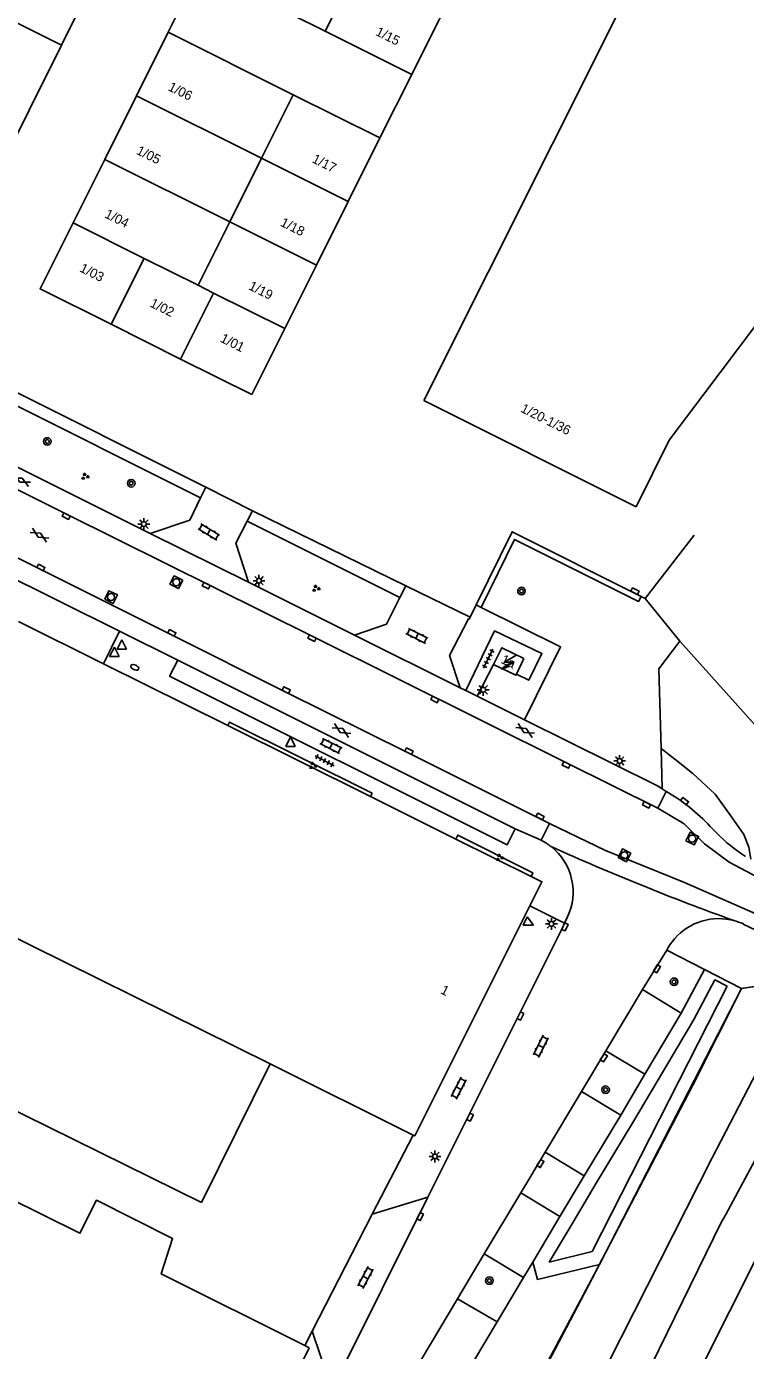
# Model space of a CAD drawing. Extents: x 135999 to 138000, y 396000 to 398501.
# Drawn here: x 136118.4 to 136194.3, y 397671.5 to 397811.3 of the extents above; entities that cross this region are included whole.
import ezdxf

# ---------------------------------------------------------------- set-up
doc = ezdxf.new("R2010")
doc.units = 0
for name, color, linetype in [('gg-afsc-hekwerk', 7, 'Continuous'), ('gg-anno-huisnummerreeks BGT', 7, 'Continuous'), ('gg-aspt-spoorlijn', 7, 'Continuous'), ('gg-bbg-gedigitaliseerde bebouwing', 7, 'Continuous'), ('gg-bbg-hoofdgebouw', 7, 'Continuous'), ('gg-bbg-tussenscheiding', 7, 'Continuous'), ('gg-knt-bronhoudergrens', 7, 'Continuous'), ('gg-knt-verharding', 7, 'Continuous'), ('gg-knt-verharding nz', 7, 'Continuous'), ('gt-grn-bladgrens', 7, 'Continuous'), ('gt-grn-groengrens', 7, 'Continuous'), ('gt-grn-vlakafsluiter', 7, 'Continuous'), ('gt-symb-boom', 7, 'Continuous'), ('gt-symb-brandkraan', 7, 'Continuous'), ('gt-symb-gesloten verharding', 7, 'Continuous'), ('gt-symb-groenvak', 7, 'Continuous'), ('gt-symb-klinker verharding', 7, 'Continuous'), ('gt-symb-kolk', 7, 'Continuous'), ('gt-symb-kolk center center', 7, 'Continuous'), ('gt-symb-lichtmast', 7, 'Continuous'), ('gt-symb-rioolschacht', 7, 'Continuous'), ('gt-symb-tegel verharding', 7, 'Continuous'), ('gt-symb-trafo symbool', 7, 'Continuous'), ('gt-symb-waterafsluiter', 7, 'Continuous'), ('gx-grn-maaiveld', 7, 'Continuous')]:
    doc.layers.add(name, color=color, linetype=linetype)

# ---------------------------------------------------------------- blocks, each defined once
blk = doc.blocks.new('gt0-BOOM')
at = {"layer": 'gt-symb-boom'}
for radius in [0.4, 0.2]:
    blk.add_circle((0, 0), radius, dxfattribs=at)
blk = doc.blocks.new('gt0-KOLK')
at = {"layer": 'gt-symb-kolk'}
blk.add_lwpolyline([(0, 0), (0.38, 0), (0.38, 0.4), (-0.38, 0.4), (-0.38, 0), (0, 0)], dxfattribs=at)
blk = doc.blocks.new('gt0-GRVAK')
at = {"layer": 'gt-symb-groenvak'}
for p, q in [((-0.11, 0.19), (-0.23, 0.24)), ((-0.18, 0.15), (0.09, 0.15)), ((-0.09, 0.21), (-0.16, 0.32)), ((-0.05, 0.21), (-0.05, 0.39)), ((0, 0.21), (0.06, 0.32)), ((0.02, 0.19), (0.13, 0.24)), ((0.26, -0.05), (0.2, 0.06)), ((0.3, -0.05), (0.3, 0.13)), ((0.35, -0.05), (0.41, 0.06)), ((-0.24, -0.23), (-0.36, -0.18)), ((-0.32, -0.26), (-0.05, -0.26)), ((-0.23, -0.21), (-0.29, -0.1)), ((-0.18, -0.2), (-0.18, -0.02)), ((-0.14, -0.21), (-0.07, -0.1)), ((-0.12, -0.23), (0, -0.18)), ((0.24, -0.07), (0.12, -0.02)), ((0.17, -0.11), (0.44, -0.11)), ((0.37, -0.07), (0.49, -0.02))]:
    blk.add_line(p, q, dxfattribs=at)
blk = doc.blocks.new('gt0-LMAST')
at = {"layer": 'gt-symb-lichtmast'}
for p, q in [((-0.18, 0.17), (-0.45, 0.44)), ((-0.01, 0.25), (-0.01, 0.62)), ((0.17, 0.17), (0.44, 0.44)), ((-0.26, 0), (-0.63, 0)), ((-0.18, -0.18), (-0.45, -0.45)), ((-0.01, -0.25), (-0.01, -0.63)), ((0.44, -0.45), (0.17, -0.18)), ((0.24, 0), (0.62, 0))]:
    blk.add_line(p, q, dxfattribs=at)
blk.add_circle((-0.01, 0), 0.25, dxfattribs=at)
blk = doc.blocks.new('gt0-RS')
at = {"layer": 'gt-symb-rioolschacht'}
blk.add_lwpolyline([(-0.5, -0.5), (0.5, -0.5), (0.5, 0.5), (-0.5, 0.5)], close=True, dxfattribs=at)
blk.add_circle((0, 0), 0.375, dxfattribs=at)
blk = doc.blocks.new('gt0-GESVH1')
at = {"layer": 'gt-symb-gesloten verharding'}
for p, q in [((-0.99, -0.26), (0.01, 0.24)), ((0.01, -0.26), (-0.99, 0.24)), ((0.01, 0.24), (1.01, -0.26)), ((1.01, 0.24), (0.01, -0.26))]:
    blk.add_line(p, q, dxfattribs=at)
blk = doc.blocks.new('gt0-KL1')
at = {"layer": 'gt-symb-klinker verharding'}
for p, q in [((-1.15, 0.3), (1.15, 0.3)), ((-1, -0.3), (-1, 0.3)), ((-0.5, 0.3), (-0.5, 0.45)), ((0, -0.3), (0, 0.3)), ((0.5, 0.3), (0.5, 0.45)), ((1, -0.3), (1, 0.3)), ((-1.15, -0.3), (1.15, -0.3)), ((-0.5, -0.45), (-0.5, -0.3)), ((0.5, -0.45), (0.5, -0.3))]:
    blk.add_line(p, q, dxfattribs=at)
blk = doc.blocks.new('gt0-TEG1')
at = {"layer": 'gt-symb-tegel verharding'}
for p, q in [((-1.12, 0), (1.13, 0)), ((-0.9, -0.25), (-0.9, 0.25)), ((-0.45, -0.25), (-0.45, 0.25)), ((0, -0.25), (0, 0.25)), ((0.45, -0.25), (0.45, 0.25)), ((0.9, -0.25), (0.9, 0.25))]:
    blk.add_line(p, q, dxfattribs=at)
blk = doc.blocks.new('gt0-HSP')
at = {"layer": 'gt-symb-trafo symbool'}
for points in [[(0.77, 0.75), (-0.53, 0), (0.47, 0), (-0.83, -0.75)], [(-0.22, -0.24), (-0.83, -0.75), (-0.08, -0.48)]]:
    blk.add_lwpolyline(points, dxfattribs=at)
blk = doc.blocks.new('gt0-WAFSL')
at = {"layer": 'gt-symb-waterafsluiter'}
for p, q in [((-0.5, -0.33), (0, 0.67)), ((0, 0.67), (0.5, -0.33)), ((0.5, -0.33), (-0.5, -0.33))]:
    blk.add_line(p, q, dxfattribs=at)
blk = doc.blocks.new('gt0-BR')
at = {"layer": 'gt-symb-brandkraan'}
for centre, radius, start, end in [((-0.24, 0), 0.206, 107.5669, 252.4331), ((0.6, -2.66), 3, 106.892, 107.5669), ((0, -0.69), 0.938, 73.108, 106.892), ((-0.6, -2.66), 3, 72.4331, 73.108), ((0.24, 0), 0.206, 287.567, 72.4331), ((0.6, 2.66), 3, 252.4331, 253.108), ((0, 0.69), 0.938, 253.108, 286.8921), ((-0.6, 2.66), 3, 286.8921, 287.567)]:
    blk.add_arc(centre, radius, start, end, dxfattribs=at)
blk = doc.blocks.new('gt0-KOLKCC')
at = {"layer": 'gt-symb-kolk center center'}
blk.add_lwpolyline([(-0.38, 0.2), (0.38, 0.2), (0.38, -0.2), (-0.38, -0.2)], close=True, dxfattribs=at)

msp = doc.modelspace()

# ---------------------------------------------------------------- linework, layer by layer
at = {"layer": 'gg-afsc-hekwerk'}
for p, q in [((136159.21, 397694.26), (136154.9, 397685.9)), ((136154.9, 397685.9), (136148.56, 397673.57)), ((136148.56, 397673.57), (136147.77, 397672.04))]:
    msp.add_line(p, q, dxfattribs=at)
msp.add_lwpolyline([(136206.22, 397710.07), (136203.26, 397711.27), (136196.98, 397710.23), (136193.86, 397709.75), (136188.71, 397699.53), (136178.32, 397679.53), (136172.59, 397668.77), (136160.48, 397645.24), (136132.77, 397588.81), (136102.14, 397526.87), (136090.23, 397502.97), (136088.59, 397499.81), (136086.91, 397496.59), (136075.23, 397472.87), (136076.15, 397472.41)], dxfattribs=at)
at = {"layer": 'gg-aspt-spoorlijn'}
msp.add_lwpolyline([(136075.9, 397441.46), (136078.9, 397447.5), (136110.62, 397511), (136126.65, 397543.4), (136168.42, 397626.98), (136182.98, 397656.49), (136206.97, 397704.32), (136208.88, 397708.17)], dxfattribs=at)
at = {"layer": 'gg-bbg-gedigitaliseerde bebouwing'}
msp.add_lwpolyline([(136103.07, 397699.88), (136104.63, 397703.04), (136136.86, 397687.15)], dxfattribs=at)
at = {"layer": 'gg-bbg-hoofdgebouw'}
for p, q in [((136122.09, 397809.32), (136126.17, 397817.51)), ((136133.36, 397810.68), (136136.71, 397817.39)), ((136162.41, 397812.93), (136159.06, 397806.23)), ((136130.02, 397803.98), (136133.36, 397810.68)), ((136113.97, 397793.01), (136122.09, 397809.32)), ((136159.06, 397806.23), (136155.71, 397799.52)), ((136126.66, 397797.26), (136130.02, 397803.98)), ((136155.71, 397799.52), (136152.36, 397792.81)), ((136123.32, 397790.57), (136126.66, 397797.26)), ((136152.36, 397792.81), (136149.01, 397786.09)), ((136149.01, 397786.09), (136145.66, 397779.39)), ((136134.67, 397776.18), (136127.34, 397779.85)), ((136145.66, 397779.39), (136142.18, 397772.43)), ((136142.18, 397772.43), (136134.67, 397776.18)), ((136160.35, 397771.8), (136182.75, 397760.59)), ((136117.58, 397748.46), (136126.54, 397744)), ((136126.54, 397744), (136139.64, 397737.49)), ((136170.9, 397744.56), (136170.1, 397742.9)), ((136139.64, 397737.49), (136154.71, 397729.99)), ((136154.71, 397729.99), (136163.73, 397725.51)), ((136163.73, 397725.51), (136171.68, 397721.55)), ((136144.13, 397701.77), (136136.86, 397687.15)), ((136159.21, 397694.26), (136144.13, 397701.77)), ((136148.25, 397671.8), (136138.89, 397653.04)), ((136147.77, 397672.04), (136148.25, 397671.8))]:
    msp.add_line(p, q, dxfattribs=at)
for points in [[(136182.75, 397760.59), (136186.24, 397767.61), (136204.5, 397791.9), (136214.73, 397812.29), (136187.44, 397825.96), (136160.35, 397771.8)], [(136127.34, 397779.85), (136119.84, 397783.6), (136123.32, 397790.57)], [(136167.69, 397743.95), (136168.55, 397745.7), (136170.9, 397744.56)], [(136170.1, 397742.9), (136170.05, 397742.8), (136167.69, 397743.95)], [(136171.68, 397721.55), (136172.79, 397721), (136171.52, 397718.47)], [(136171.52, 397718.47), (136159.38, 397694.17), (136159.21, 397694.26)], [(136100.84, 397695.39), (136124.04, 397683.89), (136125.78, 397687.38), (136133.83, 397683.35), (136132.62, 397679.61), (136147.77, 397672.04)]]:
    msp.add_lwpolyline(points, dxfattribs=at)
at = {"layer": 'gg-bbg-tussenscheiding'}
for p, q in [((136136.71, 397817.39), (136149.92, 397810.79)), ((136149.92, 397810.79), (136153.27, 397817.49)), ((136122.09, 397809.32), (136109.54, 397815.57)), ((136133.36, 397810.68), (136146.56, 397804.09)), ((136149.92, 397810.79), (136159.06, 397806.23)), ((136130.02, 397803.98), (136143.21, 397797.38)), ((136143.21, 397797.38), (136146.56, 397804.09)), ((136146.56, 397804.09), (136155.71, 397799.52)), ((136126.66, 397797.26), (136139.86, 397790.67)), ((136139.86, 397790.67), (136143.21, 397797.38)), ((136143.21, 397797.38), (136152.36, 397792.81)), ((136123.32, 397790.57), (136130.82, 397786.81)), ((136136.51, 397783.97), (136139.86, 397790.67)), ((136139.86, 397790.67), (136149.01, 397786.09)), ((136127.34, 397779.85), (136130.82, 397786.81)), ((136130.82, 397786.81), (136136.51, 397783.97)), ((136134.67, 397776.18), (136138.15, 397783.15)), ((136136.51, 397783.97), (136138.15, 397783.15)), ((136138.15, 397783.15), (136145.66, 397779.39)), ((136097.81, 397724.7), (136144.13, 397701.77))]:
    msp.add_line(p, q, dxfattribs=at)
at = {"layer": 'gg-knt-bronhoudergrens'}
msp.add_line((136193.86, 397709.75), (136198.36, 397710.41), dxfattribs=at)
msp.add_lwpolyline([(136193.86, 397709.75), (136186.37, 397695.18), (136178.88, 397680.61)], dxfattribs=at)
at = {"layer": 'gg-knt-verharding'}
for p, q in [((136137.34, 397762.67), (136114.96, 397773.86)), ((136114.47, 397766.24), (136131.46, 397757.78)), ((136136.78, 397761.53), (136137.34, 397762.67)), ((136137.34, 397762.67), (136142.24, 397760.17)), ((136142.24, 397760.17), (136141.69, 397759.08)), ((136158.45, 397752.25), (136142.24, 397760.17)), ((136141.82, 397752.62), (136131.46, 397757.78)), ((136183.69, 397750.91), (136188.86, 397757.6)), ((136128.22, 397747.46), (136108.75, 397757.15)), ((136141.82, 397752.62), (136153.01, 397747.05)), ((136157.82, 397751), (136158.45, 397752.25)), ((136183.69, 397750.91), (136183.26, 397751.13)), ((136165.23, 397748.93), (136165.87, 397750.23)), ((136128.22, 397747.46), (136126.54, 397744)), ((136128.22, 397747.46), (136134.36, 397744.39)), ((136164.18, 397741.48), (136153.01, 397747.05)), ((136169.99, 397726.59), (136134.36, 397744.39)), ((136163.04, 397744.87), (136164.18, 397741.48)), ((136165.96, 397740.6), (136167.69, 397743.95)), ((136164.18, 397741.48), (136164.76, 397741.19)), ((136164.76, 397741.19), (136165.96, 397740.6)), ((136165.96, 397740.6), (136170.95, 397738.11)), ((136185.02, 397728.76), (136185.91, 397730.54)), ((136185.5, 397730.8), (136185.91, 397730.54)), ((136172.71, 397725.38), (136173.61, 397727.16)), ((136191.24, 397726.14), (136190.56, 397726.85)), ((136169.99, 397726.59), (136172.71, 397725.38)), ((136172.71, 397725.38), (136172.76, 397725.36)), ((136175.19, 397716.62), (136171.52, 397718.47)), ((136175.47, 397717.22), (136175.19, 397716.62)), ((136193.04, 397716.91), (136192.69, 397716.99)), ((136194.05, 397716.54), (136200.08, 397713.62)), ((136185.97, 397713.78), (136183.4, 397709.62)), ((136183.4, 397709.62), (136187.5, 397707.13)), ((136187.5, 397707.13), (136183.67, 397700.68)), ((136179.55, 397703.16), (136176.97, 397698.87)), ((136183.67, 397700.68), (136179.55, 397703.16)), ((136176.97, 397698.87), (136181.11, 397696.35)), ((136181.11, 397696.35), (136177.24, 397689.97)), ((136173.14, 397692.46), (136170.57, 397688.16)), ((136177.24, 397689.97), (136173.14, 397692.46)), ((136170.57, 397688.16), (136174.69, 397685.66)), ((136174.69, 397685.66), (136171.83, 397680.86)), ((136166.7, 397681.71), (136163.89, 397676.99)), ((136170.84, 397679.21), (136166.7, 397681.71)), ((136171.83, 397680.86), (136170.84, 397679.21)), ((136163.89, 397676.99), (136168.07, 397674.54)), ((136168.07, 397674.54), (136164.19, 397668.06))]:
    msp.add_line(p, q, dxfattribs=at)
for points in [[(136047.26, 397797.39), (136054.37, 397793.87), (136082.97, 397779.59), (136092.95, 397774.6), (136109.76, 397766.26), (136122.69, 397759.78), (136148.62, 397746.9), (136175.45, 397733.51), (136185.02, 397728.76)], [(136173.61, 397727.16), (136158.68, 397734.61), (136145.72, 397741.06), (136133.65, 397747.1), (136119.84, 397753.99), (136106.87, 397760.47), (136093.91, 397766.92), (136089.99, 397768.89), (136080.05, 397773.76), (136065.32, 397781.11), (136054.8, 397786.33)], [(136131.46, 397757.78), (136135.63, 397759.17), (136136.78, 397761.53)], [(136141.69, 397759.08), (136140.51, 397756.74), (136141.82, 397752.62)], [(136183.26, 397751.13), (136169.64, 397757.95), (136165.87, 397750.23)], [(136153.01, 397747.05), (136156.4, 397748.19), (136157.82, 397751)], [(136163.04, 397744.87), (136165.04, 397748.76), (136165.13, 397748.72), (136165.23, 397748.93)], [(136164.76, 397741.19), (136167.81, 397747.49), (136172.79, 397745.1), (136171.41, 397742.27), (136170.1, 397742.9)], [(136134.36, 397744.39), (136133.51, 397742.71), (136169.14, 397724.9), (136169.99, 397726.59)], [(136170.95, 397738.11), (136185.01, 397731.12), (136185.5, 397730.8)], [(136154.71, 397729.99), (136154.87, 397730.35), (136139.83, 397737.86), (136139.64, 397737.49)], [(136171.68, 397721.55), (136171.83, 397721.96), (136163.93, 397725.92), (136163.73, 397725.51)]]:
    msp.add_lwpolyline(points, dxfattribs=at)
for centre, radius, start, end in [((136175.75, 397712.95), 20.31, 43.1848, 59.99), ((136201.85, 397736.1), 14.54, 223.1998, 238.6522), ((136170.01, 397719.98), 6.04, 51.6768, 62.9052), ((136285.79, 397973.51), 272.85, 245.7582, 250.1275), ((136169.96, 397719.91), 6.13, 334.0081, 51.7298), ((136191.46, 397710.92), 6.19, 78.5243, 142.8464), ((136191.47, 397710.94), 6.17, 65.231, 75.283), ((136191.46, 397710.92), 6.19, 142.8656, 152.48)]:
    msp.add_arc(centre, radius, start, end, dxfattribs=at)
at = {"layer": 'gg-knt-verharding nz'}
for p, q in [((136183.4, 397709.62), (136179.55, 397703.16)), ((136176.97, 397698.87), (136173.14, 397692.46)), ((136160.76, 397687.7), (136150.62, 397667.4)), ((136154.9, 397685.9), (136160.76, 397687.7)), ((136170.57, 397688.16), (136166.7, 397681.71)), ((136163.89, 397676.99), (136160.04, 397670.53)), ((136150.62, 397667.4), (136148.56, 397673.57))]:
    msp.add_line(p, q, dxfattribs=at)
for points in [[(136185.02, 397728.76), (136187.82, 397727.13), (136189.95, 397725), (136192.56, 397723.07), (136196.21, 397721.12), (136204.45, 397717.04), (136209.71, 397714.25)], [(136173.61, 397727.16), (136179.49, 397724.29), (136187.85, 397720.92), (136196.82, 397716.99), (136203.48, 397713.62), (136208.21, 397711.23)], [(136175.19, 397716.62), (136174.95, 397716.08), (136160.76, 397687.7)]]:
    msp.add_lwpolyline(points, dxfattribs=at)
at = {"layer": 'gt-grn-bladgrens'}
msp.add_line((136191.71, 397685.03), (136192.19, 397685.88), dxfattribs=at)
at = {"layer": 'gt-grn-groengrens'}
for p, q in [((136136.78, 397761.53), (136114.39, 397772.74)), ((136157.82, 397751), (136141.69, 397759.08)), ((136183.69, 397750.91), (136187.36, 397746.41)), ((136165.87, 397750.23), (136166.4, 397749.96)), ((136187.36, 397746.41), (136206.95, 397724.49)), ((136185.5, 397730.8), (136185.38, 397735.08)), ((136185.97, 397713.78), (136189.94, 397711.75)), ((136189.94, 397711.75), (136187.5, 397707.13)), ((136189.94, 397711.75), (136193.86, 397709.75)), ((136178.1, 397681.97), (136192.35, 397709.97)), ((136183.67, 397700.68), (136181.11, 397696.35)), ((136177.24, 397689.97), (136174.69, 397685.66)), ((136171.83, 397680.86), (136172.33, 397679)), ((136172.33, 397679), (136178.88, 397680.61)), ((136170.84, 397679.21), (136168.07, 397674.54))]:
    msp.add_line(p, q, dxfattribs=at)
for points in [[(136183.26, 397751.13), (136182.99, 397750.59), (136169.92, 397757.14), (136166.4, 397749.96)], [(136170.95, 397738.11), (136174.77, 397745.8), (136166.4, 397749.96)], [(136187.36, 397746.41), (136185.14, 397743.48), (136185.38, 397735.08)], [(136185.38, 397735.08), (136186.84, 397733.95), (136188.71, 397732.44), (136191.09, 397730.24), (136192.8, 397727.86), (136194.09, 397725.99), (136194.63, 397724.65), (136194.83, 397723.4)], [(136178.1, 397681.97), (136173.57, 397680.85), (136175.98, 397684.89), (136178.52, 397689.2), (136182.4, 397695.58), (136184.96, 397699.92), (136188.81, 397706.4), (136191.05, 397710.64), (136192.35, 397709.97)]]:
    msp.add_lwpolyline(points, dxfattribs=at)
at = {"layer": 'gt-grn-vlakafsluiter'}
msp.add_line((136158.45, 397752.25), (136165.23, 397748.93), dxfattribs=at)
msp.add_lwpolyline([(136178.88, 397680.61), (136166.53, 397657.01), (136160.48, 397645.24), (136147.38, 397618.57), (136132.77, 397588.81), (136103.22, 397529.06), (136086.99, 397496.75)], dxfattribs=at)
at = {"layer": 'gx-grn-maaiveld'}
msp.add_line((136191.71, 397685.03), (136168.74, 397638.06), dxfattribs=at)
for points in [[(136079.12, 397470.95), (136089.3, 397490.11), (136093.09, 397497.58), (136116.32, 397543.68), (136148.79, 397608.63), (136171.6, 397654), (136190.78, 397691.87), (136195.5, 397701), (136198.41, 397705.89), (136200.96, 397709.86), (136201.44, 397710.49), (136201.81, 397710.81)], [(136204.48, 397706.86), (136204.15, 397706.41), (136203.28, 397706.22), (136202.24, 397704.56), (136192.19, 397685.88)]]:
    msp.add_lwpolyline(points, dxfattribs=at)

# ---------------------------------------------------------------- block references
at = {"layer": 'gt-symb-boom'}
for p in [(136120.6, 397767.48), (136129.46, 397763.07), (136170.64, 397751.69), (136186.74, 397710.44), (136179.52, 397699.05), (136167.25, 397678.89)]:
    msp.add_blockref('gt0-BOOM', p, dxfattribs=at)
at = {"layer": 'gt-symb-brandkraan', "rotation": -24.77113890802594}
msp.add_blockref('gt0-BR', (136129.83, 397743.63), dxfattribs=at)
at = {"layer": 'gt-symb-gesloten verharding'}
for p, rotation in [((136117.82, 397763.41), -26.02719868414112), ((136119.77, 397757.6), -31.003067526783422), ((136151.64, 397736.98), -31.003067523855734), ((136171.02, 397736.99), -31.003067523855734)]:
    msp.add_blockref('gt0-GESVH1', p, dxfattribs=dict(at, rotation=rotation))
at = {"layer": 'gt-symb-groenvak'}
for p in [(136124.57, 397763.78), (136148.95, 397751.96), (136148.62, 397733.26), (136168.32, 397723.55)]:
    msp.add_blockref('gt0-GRVAK', p, dxfattribs=at)
at = {"layer": 'gt-symb-klinker verharding'}
for p, rotation in [((136137.65, 397757.92), -31.003067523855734), ((136159.61, 397746.95), -26.565051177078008), ((136150.54, 397735.34), 153.46056160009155), ((136172.68, 397703.63), -116.41137489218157), ((136164.01, 397699.21), -117.46222718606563), ((136154.17, 397679.22), -118.153346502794)]:
    msp.add_blockref('gt0-KL1', p, dxfattribs=dict(at, rotation=rotation))
at = {"layer": 'gt-symb-kolk'}
for p, rotation in [((136122.69, 397759.78), 153.38370037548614), ((136119.84, 397753.99), -26.565051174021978), ((136137.46, 397752.44), 153.58862510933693), ((136182.53, 397751.5), -26.60114300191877), ((136133.65, 397747.1), -26.488178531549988), ((136148.62, 397746.9), 153.58862511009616), ((136145.72, 397741.06), -26.565051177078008), ((136161.59, 397740.43), 153.51182146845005), ((136158.68, 397734.61), -26.488178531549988), ((136175.45, 397733.51), 153.46056159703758), ((136187.73, 397729.36), -37.23665897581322), ((136172.51, 397727.71), -26.539438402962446), ((136183.93, 397729.3), 153.63994178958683), ((136175.04, 397716.32), -115.33527699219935), ((136184.78, 397711.92), -120.79671391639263), ((136179.16, 397702.53), -121.79891282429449), ((136172.47, 397691.36), -121.13079914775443)]:
    msp.add_blockref('gt0-KOLK', p, dxfattribs=dict(at, rotation=rotation))
at = {"layer": 'gt-symb-kolk center center'}
for p, rotation in [((136170.54, 397706.83), 64.02428534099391), ((136165.21, 397696.15), -116.82140642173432), ((136159.95, 397685.66), 63.306770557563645)]:
    msp.add_blockref('gt0-KOLKCC', p, dxfattribs=dict(at, rotation=rotation))
at = {"layer": 'gt-symb-lichtmast'}
for p in [(136130.8, 397758.76), (136142.95, 397752.78), (136166.61, 397741.27), (136181.01, 397733.76), (136173.81, 397716.55), (136161.52, 397692.01)]:
    msp.add_blockref('gt0-LMAST', p, dxfattribs=at)
at = {"layer": 'gt-symb-rioolschacht'}
for p, rotation in [((136134.22, 397752.62), 152.53777281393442), ((136127.33, 397751.06), -25.71951295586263), ((136188.65, 397725.56), -26.488178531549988), ((136181.5, 397723.79), -27.179734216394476)]:
    msp.add_blockref('gt0-RS', p, dxfattribs=dict(at, rotation=rotation))
at = {"layer": 'gt-symb-tegel verharding'}
for p, rotation in [((136167.14, 397744.55), -116.15525375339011), ((136149.86, 397733.78), -27.769212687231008)]:
    msp.add_blockref('gt0-TEG1', p, dxfattribs=dict(at, rotation=rotation))
at = {"layer": 'gt-symb-trafo symbool'}
msp.add_blockref('gt0-HSP', (136169.37, 397744.2), dxfattribs=at)
at = {"layer": 'gt-symb-waterafsluiter'}
for p in [(136128.46, 397745.88), (136127.68, 397745.1), (136146.26, 397735.62)]:
    msp.add_blockref('gt0-WAFSL', p, dxfattribs=at)
at = {"layer": 'gt-symb-waterafsluiter', "rotation": -116.56505117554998}
msp.add_blockref('gt0-WAFSL', (136171.32, 397716.71), dxfattribs=at)

# ---------------------------------------------------------------- texts
at = {"layer": 'gg-anno-huisnummerreeks BGT'}
for s, rotation, p in [('1/15', 333.5, (136155.16, 397810.41)), ('1/06', 333.5, (136133.27, 397804.59)), ('1/05', 333.5, (136129.92, 397797.87)), ('1/17', 333.5, (136148.46, 397796.99)), ('1/04', 333.5, (136126.57, 397791.17)), ('1/18', 333.5, (136145.11, 397790.28)), ('1/03', 333.4, (136123.94, 397785.46)), ('1/19', 333.5, (136141.76, 397783.57)), ('1/02', 333.4, (136131.35, 397781.76)), ('1/01', 333.4, (136138.77, 397778.05)), ('1/20-1/36', 333.4, (136170.47, 397770.65)), ('1a', 334, (136168.38, 397744.14)), ('1', 333.4, (136162.02, 397709.26))]:
    msp.add_text(s, height=1, rotation=rotation, dxfattribs=at).set_placement(p)

doc.saveas('drawing.dxf')
